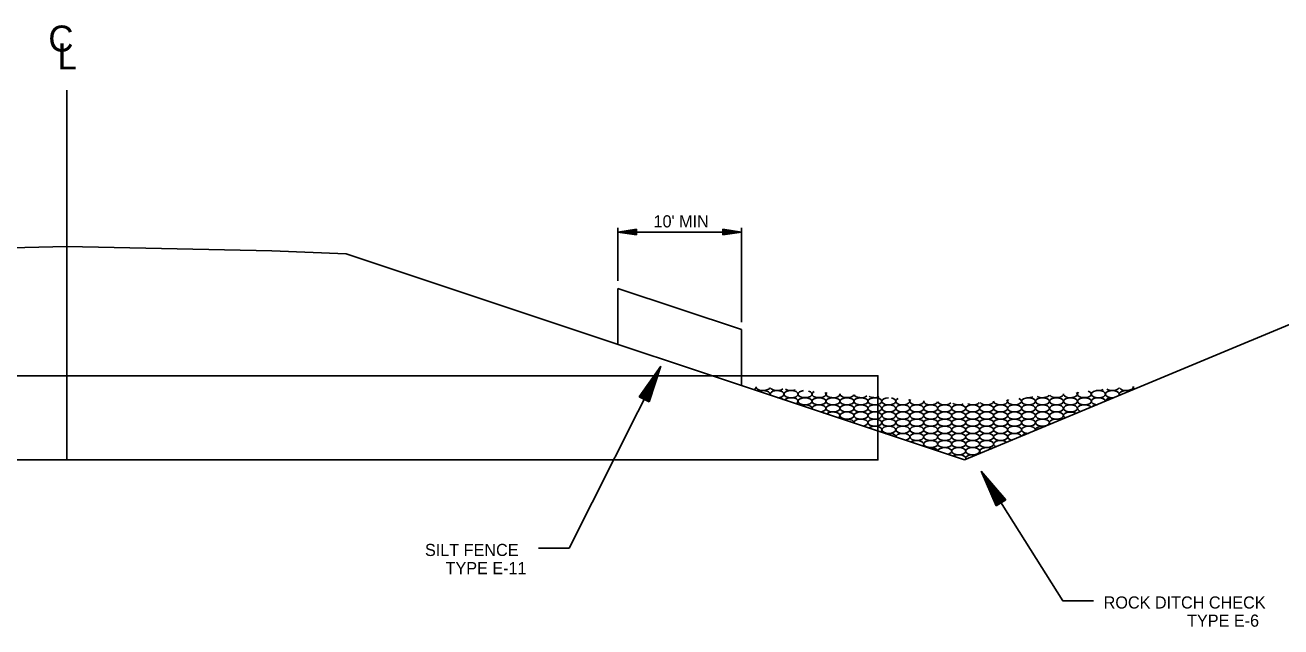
# Model space of a CAD drawing. Extents: x 3575 to 11445, y 9479 to 13278.
# Drawn here: x 4243 to 4917, y 12956 to 13278 of the extents above; entities that cross this region are included whole.
import ezdxf

# ---------------------------------------------------------------- set-up
doc = ezdxf.new("R2010")
doc.units = 0
for name, color, linetype in [('Agg Base Course Text', 7, 'Continuous'), ('Aggregate Base Course', 7, 'Continuous'), ('CL Construction', 7, 'Continuous'), ('Default', 7, 'Continuous'), ('R_Culvert', 7, 'Continuous'), ('R_Dimension', 7, 'Continuous'), ('STAMP_PE_CRAFTON-SIGNATURE', 7, 'Continuous')]:
    doc.layers.add(name, color=color, linetype=linetype)

msp = doc.modelspace()

# ---------------------------------------------------------------- linework, layer by layer
at = {"layer": 'Agg Base Course Text'}
for points in [[(4518.6, 12997.7), (4535.05, 12997.7), (4584.23, 13095.5)], [(4816.47, 12969.51), (4800.02, 12969.51), (4756.26, 13038.99)]]:
    msp.add_lwpolyline(points, dxfattribs=at)
at = {"layer": 'Aggregate Base Course'}
for centre, start_param, end_param in [((4624.18, 13084.23), 0.408052, 0.448145), ((4631.68, 13084.23), 2.726487, 2.825563), ((4631.68, 13084.23), 5.441418, 6.374353), ((4639.18, 13084.23), 3.051764, 6.049076), ((4639.18, 13080.41), 6.0301, 8.520066), ((4646.68, 13080.41), 4.81896, 9.731206), ((4646.68, 13084.23), 3.385252, 5.715588), ((4654.18, 13084.23), 3.779279, 5.321561), ((4661.68, 13080.41), 1.773646, 7.327194), ((4669.18, 13080.41), 2.321455, 6.779385), ((4676.68, 13080.41), 2.686285, 6.414555), ((4684.18, 13080.41), 3.012999, 6.087841), ((4691.68, 13080.41), 3.343489, 5.757352), ((4699.18, 13080.41), 3.725217, 5.375623), ((4781.68, 13080.41), 4.461265, 5.366463), ((4789.18, 13080.41), 3.865604, 5.962124), ((4796.68, 13080.41), 3.442076, 6.385653), ((4804.18, 13080.41), 3.03692, 6.790808), ((4811.68, 13080.41), 2.565397, 7.262331), ((4819.18, 13084.23), 4.373827, 5.453902), ((4826.68, 13080.41), 5.789959, 11.288036), ((4826.68, 13084.23), 3.8182, 6.009529), ((4834.18, 13080.41), 1.033463, 3.478161), ((4834.18, 13084.23), 3.400321, 6.427407), ((4841.68, 13084.23), 2.992946, 3.768581), ((4646.68, 13076.58), 0.540895, 1.442901), ((4654.18, 13076.58), 5.508855, 9.041312), ((4661.68, 13072.76), 6.100297, 8.449869), ((4669.18, 13072.76), 4.916973, 9.633193), ((4706.68, 13076.58), 1.642181, 7.458659), ((4714.18, 13076.58), 2.271543, 6.829297), ((4721.68, 13076.58), 2.645589, 6.455251), ((4729.18, 13076.58), 2.974285, 6.126555), ((4736.68, 13076.58), 3.302379, 5.798461), ((4744.18, 13076.58), 3.673732, 5.427108), ((4751.68, 13076.58), 3.914342, 5.913386), ((4759.18, 13076.58), 3.484004, 6.343724), ((4766.68, 13076.58), 3.080291, 6.747438), ((4774.18, 13076.58), 2.622253, 7.205475), ((4811.68, 13072.76), 0.31991, 4.191714), ((4819.18, 13076.58), 6.273063, 10.804932), ((4819.18, 13072.76), 1.82428, 2.687344), ((4826.68, 13076.58), 1.359997, 3.151628), ((4669.18, 13068.93), 0.72912, 1.254676), ((4676.68, 13068.93), 5.81087, 8.974765), ((4676.68, 13068.93), 5.575401, 5.81087), ((4684.18, 13065.11), 6.172623, 8.377543), ((4691.68, 13065.11), 5.006141, 9.544026), ((4796.68, 13065.11), 0.896427, 3.615197), ((4804.18, 13068.93), 0.611345, 3.900279), ((4699.18, 13061.28), 5.641378, 8.908788), ((4706.68, 13057.46), 6.247704, 8.302462), ((4714.18, 13057.46), 5.089068, 9.461098), ((4774.18, 13057.46), 0.174478, 4.337146), ((4781.68, 13061.28), 6.086077, 10.991917), ((4781.68, 13057.46), 1.574469, 2.937156), ((4789.18, 13061.28), 1.200876, 3.310748), ((4721.68, 13053.63), 5.707081, 8.843085), ((4759.18, 13049.81), 0.763337, 3.748287), ((4766.68, 13053.63), 0.478345, 4.033279), ((4729.18, 13049.81), 0.04318, 1.940616), ((4736.68, 13049.81), 5.167386, 9.38278), ((4744.18, 13045.98), 5.839893, 8.77737), ((4751.68, 13045.98), 1.05509, 3.456534)]:
    msp.add_ellipse(centre, major_axis=(3.75, 0), ratio=0.51, start_param=start_param, end_param=end_param, dxfattribs=at)
for centre in [(4654.18, 13080.41), (4819.18, 13080.41), (4661.68, 13076.58), (4669.18, 13076.58), (4676.68, 13076.58), (4676.68, 13072.76), (4684.18, 13076.58), (4684.18, 13072.76), (4691.68, 13076.58), (4691.68, 13072.76), (4699.18, 13076.58), (4699.18, 13072.76), (4706.68, 13072.76), (4714.18, 13072.76), (4721.68, 13072.76), (4729.18, 13072.76), (4736.68, 13072.76), (4744.18, 13072.76), (4751.68, 13072.76), (4759.18, 13072.76), (4766.68, 13072.76), (4774.18, 13072.76), (4781.68, 13076.58), (4781.68, 13072.76), (4789.18, 13076.58), (4789.18, 13072.76), (4796.68, 13076.58), (4796.68, 13072.76), (4804.18, 13076.58), (4804.18, 13072.76), (4811.68, 13076.58), (4684.18, 13068.93), (4691.68, 13068.93), (4699.18, 13068.93), (4699.18, 13065.11), (4706.68, 13068.93), (4706.68, 13065.11), (4714.18, 13068.93), (4714.18, 13065.11), (4721.68, 13068.93), (4721.68, 13065.11), (4729.18, 13068.93), (4729.18, 13065.11), (4736.68, 13068.93), (4736.68, 13065.11), (4744.18, 13068.93), (4744.18, 13065.11), (4751.68, 13068.93), (4751.68, 13065.11), (4759.18, 13068.93), (4759.18, 13065.11), (4766.68, 13068.93), (4766.68, 13065.11), (4774.18, 13068.93), (4774.18, 13065.11), (4781.68, 13068.93), (4781.68, 13065.11), (4789.18, 13068.93), (4789.18, 13065.11), (4796.68, 13068.93), (4706.68, 13061.28), (4714.18, 13061.28), (4721.68, 13061.28), (4721.68, 13057.46), (4729.18, 13061.28), (4729.18, 13057.46), (4736.68, 13061.28), (4736.68, 13057.46), (4744.18, 13061.28), (4744.18, 13057.46), (4751.68, 13061.28), (4751.68, 13057.46), (4759.18, 13061.28), (4759.18, 13057.46), (4766.68, 13061.28), (4766.68, 13057.46), (4774.18, 13061.28), (4729.18, 13053.63), (4736.68, 13053.63), (4744.18, 13053.63), (4751.68, 13053.63), (4759.18, 13053.63), (4744.18, 13049.81), (4751.68, 13049.81)]:
    msp.add_ellipse(centre, major_axis=(3.75, 0), ratio=0.51, dxfattribs=at)
at = {"layer": 'CL Construction'}
msp.add_line((4265.38, 13045.08), (4265.38, 13243.58), dxfattribs=at)
at = {"layer": 'Default'}
for p, q in [((4265.38, 13159.56), (4155.4, 13157.36)), ((4265.38, 13159.56), (4375.36, 13157.36)), ((4375.36, 13157.36), (4415.33, 13155.76)), ((4747.37, 13045.08), (4415.33, 13155.76)), ((4561.14, 13137.15), (4561.14, 13107.15)), ((4747.37, 13045.08), (4941.21, 13125.85))]:
    msp.add_line(p, q, dxfattribs=at)
msp.add_lwpolyline([(4627.55, 13085.02), (4627.55, 13115.02), (4561.14, 13137.15)], dxfattribs=at)
at = {"layer": 'R_Culvert'}
msp.add_lwpolyline([(3830, 13045.08), (4700.77, 13045.08), (4700.77, 13090.24), (3830, 13090.24)], close=True, dxfattribs=at)
at = {"layer": 'R_Dimension'}
for p, q in [((4561.14, 13169.64), (4561.14, 13141.15)), ((4571.14, 13168.87), (4561.14, 13167.37)), ((4627.55, 13167.37), (4561.14, 13167.37)), ((4571.14, 13165.87), (4561.14, 13167.37)), ((4571.14, 13168.62), (4562.81, 13167.37)), ((4571.14, 13166.12), (4562.81, 13167.37)), ((4571.14, 13168.36), (4564.53, 13167.37)), ((4571.14, 13166.37), (4564.53, 13167.37)), ((4571.14, 13168.11), (4566.2, 13167.37)), ((4571.14, 13166.62), (4566.2, 13167.37)), ((4571.14, 13167.85), (4567.89, 13167.37)), ((4571.14, 13166.88), (4567.89, 13167.37)), ((4571.14, 13167.6), (4569.56, 13167.37)), ((4571.14, 13167.13), (4569.56, 13167.37)), ((4571.14, 13168.87), (4571.14, 13165.87)), ((4617.55, 13168.87), (4627.55, 13167.37)), ((4617.55, 13165.87), (4617.55, 13168.87)), ((4617.55, 13168.62), (4625.88, 13167.37)), ((4617.55, 13168.36), (4624.16, 13167.37)), ((4617.55, 13168.11), (4622.5, 13167.37)), ((4617.55, 13167.86), (4620.8, 13167.37)), ((4617.55, 13167.6), (4619.13, 13167.37)), ((4617.55, 13165.87), (4627.55, 13167.37)), ((4617.55, 13166.88), (4620.8, 13167.37)), ((4617.55, 13166.37), (4624.16, 13167.37)), ((4617.55, 13166.12), (4625.88, 13167.37)), ((4617.55, 13166.62), (4622.5, 13167.37)), ((4617.55, 13167.13), (4619.13, 13167.37)), ((4627.55, 13119.02), (4627.55, 13169.64))]:
    msp.add_line(p, q, dxfattribs=at)
at = {"layer": 'STAMP_PE_CRAFTON-SIGNATURE'}
for p, q in [((4572.57, 13078.98), (4584.23, 13095.5)), ((4573.01, 13078.75), (4582.73, 13092.51)), ((4577.48, 13076.51), (4582.73, 13092.51)), ((4577.93, 13076.28), (4584.23, 13095.5)), ((4573.47, 13078.52), (4581.19, 13089.44)), ((4573.92, 13078.3), (4579.69, 13086.46)), ((4576.58, 13076.96), (4579.69, 13086.46)), ((4577.03, 13076.73), (4581.19, 13089.44)), ((4577.93, 13076.28), (4572.57, 13078.98)), ((4574.37, 13078.07), (4578.17, 13083.44)), ((4574.83, 13077.84), (4576.67, 13080.45)), ((4575.67, 13077.42), (4576.67, 13080.45)), ((4576.12, 13077.19), (4578.17, 13083.44)), ((4764.38, 13020.47), (4756.26, 13038.99)), ((4769.46, 13023.67), (4756.26, 13038.99)), ((4764.81, 13020.73), (4758.04, 13036.16)), ((4769.04, 13023.4), (4758.04, 13036.16)), ((4768.61, 13023.13), (4759.88, 13033.25)), ((4765.24, 13021.01), (4759.88, 13033.25)), ((4765.66, 13021.27), (4761.65, 13030.44)), ((4768.18, 13022.86), (4761.65, 13030.44)), ((4767.75, 13022.59), (4763.46, 13027.57)), ((4766.1, 13021.55), (4763.46, 13027.57)), ((4764.38, 13020.47), (4769.46, 13023.67)), ((4767.32, 13022.32), (4765.24, 13024.74)), ((4766.52, 13021.82), (4765.24, 13024.74))]:
    msp.add_line(p, q, dxfattribs=at)

# ---------------------------------------------------------------- texts
at = {"layer": 'Agg Base Course Text'}
for s, p in [('SILT FENCE', (4457.64, 12993.55)), ('TYPE E-11', (4468.7, 12983.8)), ('ROCK DITCH CHECK', (4822, 12965.36)), ('TYPE E-6', (4866.78, 12955.61))]:
    msp.add_text(s, height=6.5, dxfattribs=at).set_placement(p)
at = {"layer": 'CL Construction'}
for s, p in [('C', (4255.45, 13264.24)), ('L', (4260.38, 13254.69))]:
    msp.add_text(s, height=14, dxfattribs=at).set_placement(p)
at = {"layer": 'R_Dimension'}
msp.add_text("10' MIN", height=6.5, dxfattribs=at).set_placement((4580.35, 13169.9))

doc.saveas('drawing.dxf')
